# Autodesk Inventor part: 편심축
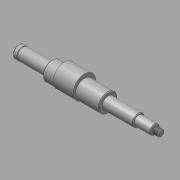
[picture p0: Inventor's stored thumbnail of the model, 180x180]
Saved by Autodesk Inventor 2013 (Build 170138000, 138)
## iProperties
Created: 2015-09
Part Number: 편심축
Material: 강철, 연강
Document SubType Name: Modeling
Designer: mduedu
Density: 1 g/cm^3
Author: mduedu
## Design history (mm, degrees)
sketch "스케치1"
  geometry: L1 (-88.5, 0)-(88.5, 0); L2 (-88.5, 0)-(-88.5, 7.5); L3 (-88.5, 7.5)-(-47.35, 7.5); L4 (-47.35, 7.5)-(-47.35, 11.5); L5 (-47.35, 11.5)-(22.65, 11.5); L6 (22.65, 11.5)-(22.65, 7.5); L7 (22.65, 7.5)-(60.65, 7.5); L8 (60.65, 7.5)-(60.65, 6); L9 (60.65, 6)-(80.65, 6); L10 (80.65, 6)-(80.65, 3); L11 (80.65, 3)-(81.65, 3); L12 (81.65, 3)-(81.65, 4); L13 (81.65, 4)-(88.5, 4); L14 (88.5, 4)-(88.5, 0); 2 further points
  constraints: 28 end point, 10 parallel, 2 perpendicular, 1 coincident, 1 collinear, 1 horizontal, 1 midpoint
  dimensions: "d0" = 41.15 distance of L2.end L3.end; "d2" = 70 distance of L4.end L5.end; "d3" = 38 distance of L6.end L7.end; "d4" = 177 distance of L1.start L1.end; "d5" = 20 distance of L8.end L9.end; "d6" = 1 distance of L10.end L11.end; "d7" = 8 diameter of L13 L1; "d8" = 6 diameter of L11 L1; "d9" = 12 diameter of L9 L1; "d10" = 15 diameter of L7 L1; "d11" = 23 diameter of L5 L1; "d12" = 15 diameter of L3 L1
revolve "회전1" sketch "스케치1" stored, may be unused: angle "d13" = 90 deg
sketch "스케치2"
  geometry: L1 (-88.5, 7.5)-(-47.35, 7.5) reference; L2 (-88.5, -7.5)-(-88.5, 7.5) reference; L3 (88.5, -4)-(88.5, 4) reference; L4 (-88.5, 0)-(88.5, 0); L5 (-83.5, 7.5)-(-82.35, 7.5); L6 (-82.35, 7.5)-(-82.35, 7.15); L7 (-82.35, 7.15)-(-83.5, 7.15); L8 (-83.5, 7.15)-(-83.5, 7.5); 1 further point
  constraints: 10 end point, 2 midpoint, 2 parallel, 1 horizontal, 1 perpendicular, 1 point on line
  dimensions: "d14" = 5 distance between parallel lines of L8 L2; "d15" = 14.3 diameter of L7 L4; "d16" = 1.15 distance of L6.end L7.end
revolve "회전2" sketch "스케치2" stored, may be unused: angle "d17" = 90 deg
node "작업 평면1"
sketch "스케치3"
  geometry: C1 r 11.5 at (0, 0) reference; C2 r 14 at (0, 2.5); 1 further point
  constraints: 1 centre point, 1 tangent, 1 vertical alignment
  dimensions: "d19" = 28 diameter of C2
extrude "돌출1" join sketch "스케치3" distance "d21" = 25; taper "d22" = 0 deg
node "작업 평면2"
sketch "스케치4"
  geometry: L1 (10, 7.5)-(10, -7.5) reference; L2 (-10, 6)-(-10, -6) reference; L3 (10, 0)-(-10, 0); L4 (-5, -2)-(3, -2); L5 (3, 2)-(-5, 2); A1 r 2 centre (3, 0) between (3, -2) and (3, 2); A2 r 2 centre (-5, 0) between (-5, 2) and (-5, -2); 1 further point
  constraints: 6 end point, 4 point on circle, 4 tangent, 2 centre point, 2 midpoint, 2 parallel, 1 point on line
  dimensions: "d23" = 4 distance between parallel lines of L5 L4; "d25" = 12 dimension on A2 A1; "d26" = 3 distance edge to line of A2 L2
extrude "돌출2" cut sketch "스케치4" distance "d27" = 2.5; taper "d28" = 0 deg
chamfer "모따기1" distance "d29" = 1; stored, may be unused: second distance "d30" = 2, angle "d31" = 45 deg
feature "스레드1" dims "d32" = 10, "d33" = 0
chamfer "모따기2" distance "d34" = 1; stored, may be unused: second distance "d35" = 2, angle "d36" = 45 deg
chamfer "모따기3" distance "d37" = 1; stored, may be unused: second distance "d38" = 2, angle "d39" = 45 deg
node "솔리드1"
other parameters: "d18" = -29.5
